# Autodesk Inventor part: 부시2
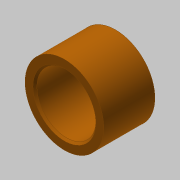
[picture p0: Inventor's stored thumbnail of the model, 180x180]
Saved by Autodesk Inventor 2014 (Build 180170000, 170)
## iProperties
Created: 2016-08
Part Number: 부시2
Material: 강철, 탄소
Document SubType Name: Modeling
Designer: mduedu
Density: 7.87 g/cm^3
Appearance: 주황색
Author: mduedu
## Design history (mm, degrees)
sketch "스케치1"
  geometry: C1 r 7.5 at (0, 0); C2 r 10 at (0, 0); 1 further point
  constraints: 2 centre point, 2 coincident
  dimensions: "d0" = 15 diameter of C1; "d1" = 20 diameter of C2
extrude "돌출1" new body sketch "스케치1" stored distance "d2" = 13; taper "d3" = 0 deg
chamfer "모따기1" distance "d4" = 0.5; stored, may be unused: second distance "d5" = 2, angle "d6" = 45 deg
node "솔리드1"
